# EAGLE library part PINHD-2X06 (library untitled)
PIN HEADER
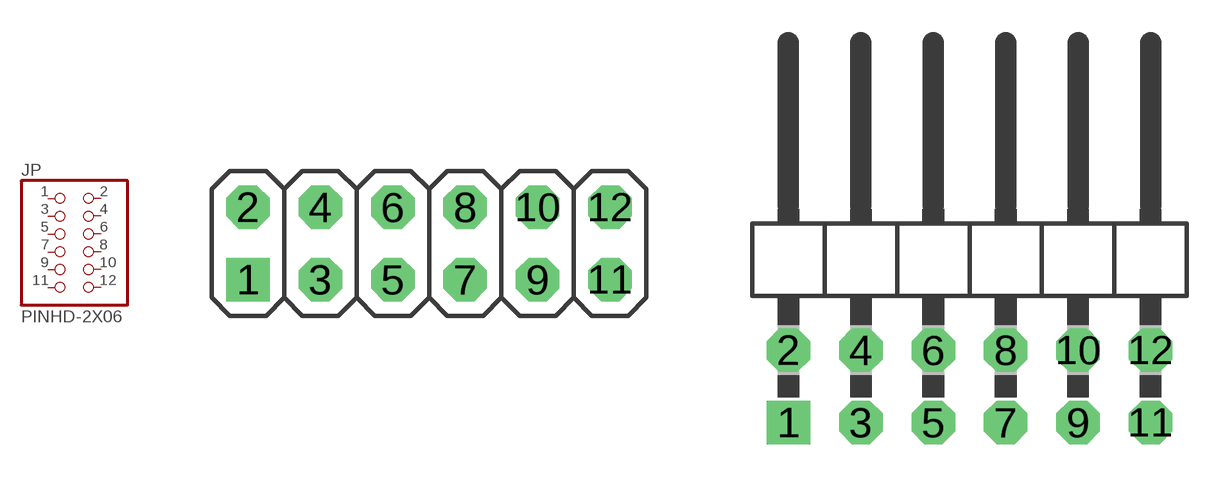
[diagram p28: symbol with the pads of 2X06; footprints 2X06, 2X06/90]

Designator prefix JP

## PINHD-2X06_2.54  [2X06]
1  1  pas
2  2  pas
3  3  pas
4  4  pas
5  5  pas
6  6  pas
7  7  pas
8  8  pas
9  9  pas
10  10  pas
11  11  pas
12  12  pas

## PINHD-2X06_2.54-90°  [2X06/90]
Pads as for 2X06

## PINHD-2X06_2.00  [2X06M]
Pads as for 2X06

## PINHD-2X06_2.54-SMD  [2X06SMD]
Pads as for 2X06

## PINHD-2X06_MICROMATCH  [MICROMATCH-12]
Pads as for 2X06

## PINHD-2X06_2.54-SMD-90°  [2X06SMD/90]
Pads as for 2X06

## Footprint 2X06 (pad centres in mm)
PIN HEADER - 2.54
drill 1.016 square: 1 -6.35,-1.27
drill 1.016 octagon: 2 -6.35,1.27; 3 -3.81,-1.27; 4 -3.81,1.27; 5 -1.27,-1.27; 6 -1.27,1.27; 7 1.27,-1.27; 8 1.27,1.27; 9 3.81,-1.27; 10 3.81,1.27; 11 6.35,-1.27; 12 6.35,1.27

## Footprint 2X06/90 (pad centres in mm)
PIN HEADER - 2.54 90°
drill 1.016 square: 1 -6.35,-6.35
drill 1.016 octagon: 2 -6.35,-3.81; 3 -3.81,-6.35; 4 -3.81,-3.81; 5 -1.27,-6.35; 6 -1.27,-3.81; 7 1.27,-6.35; 8 1.27,-3.81; 9 3.81,-6.35; 10 3.81,-3.81; 11 6.35,-6.35; 12 6.35,-3.81

## Footprint 2X06M (pad centres in mm)
PIN HEADER - 2
drill 0.914 square: 1 -5,-1
drill 0.914 round: 2 -5,1; 3 -3,-1; 4 -3,1; 5 -1,-1; 6 -1,1; 7 1,-1; 8 1,1; 9 3,-1; 10 3,1; 11 5,-1; 12 5,1

## Footprint 2X06SMD (pad centres in mm)
PIN HEADER - 2.54 SMD
smd 1.016 x 3.302: 1 -1.27,-3.81; 2 -1.27,1.27; 3 1.27,-3.81; 4 1.27,1.27; 5 3.81,-3.81; 6 3.81,1.27; 7 6.35,-3.81; 8 6.35,1.27; 9 8.89,-3.81; 10 8.89,1.27; 11 11.43,-3.81; 12 11.43,1.27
